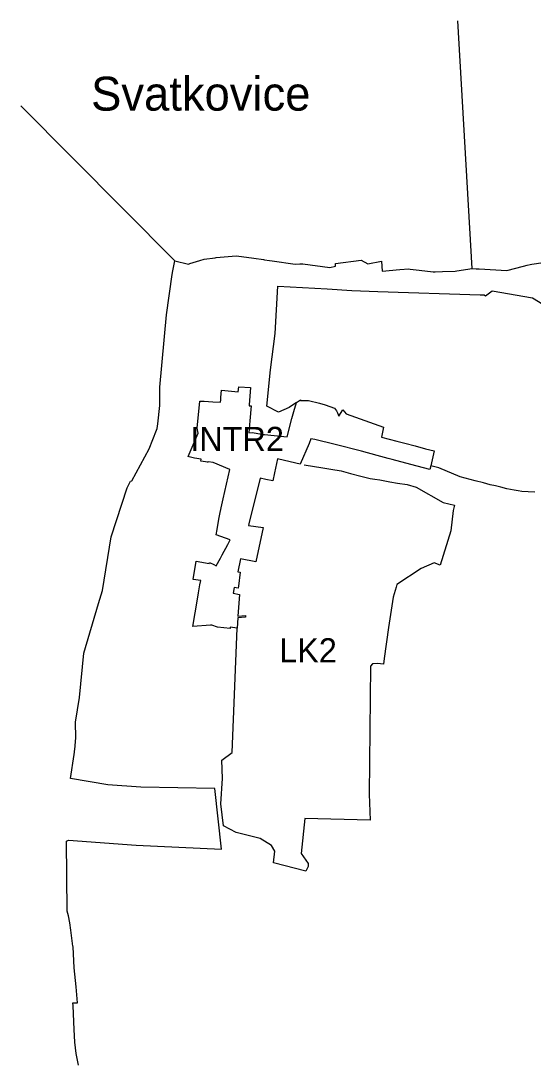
# Model space of a CAD drawing. Extents: x -761751 to -755187, y -1130961 to -1125705.
# Drawn here: x -758140 to -757082, y -1127845 to -1125705 of the extents above; entities that cross this region are included whole.
import ezdxf

# ---------------------------------------------------------------- set-up
doc = ezdxf.new("R2010")
doc.units = 0
for name, color, linetype in [('Vrstva 1', 7, 'Continuous'), ('Vrstva 13', 7, 'Continuous'), ('Vrstva 2', 7, 'Continuous'), ('Vrstva 3', 7, 'Continuous')]:
    doc.layers.add(name, color=color, linetype=linetype)

msp = doc.modelspace()

# ---------------------------------------------------------------- linework, layer by layer
at = {"layer": 'Vrstva 1'}
for p, q in [((-757208.02, -1126215.66), (-757237.56, -1125704.51)), ((-757761.4, -1126196.07), (-757738.61, -1126193.29)), ((-757738.61, -1126193.29), (-757736.19, -1126192.99)), ((-757736.19, -1126192.99), (-757694.99, -1126189.25)), ((-757694.99, -1126189.25), (-757683.91, -1126190.83)), ((-757683.91, -1126190.83), (-757658.81, -1126194.41)), ((-757658.81, -1126194.41), (-757638.53, -1126197.3)), ((-757825.98, -1126220.3), (-757821.94, -1126199.75)), ((-757821.94, -1126199.75), (-757793.4, -1126206.5)), ((-757793.4, -1126206.5), (-757790.46, -1126205.54)), ((-757790.46, -1126205.54), (-757770.03, -1126198.89)), ((-757770.03, -1126198.89), (-757761.4, -1126196.07)), ((-757638.53, -1126197.3), (-757636.67, -1126197.56)), ((-757636.67, -1126197.56), (-757626.07, -1126199.08)), ((-757626.07, -1126199.08), (-757621, -1126199.8)), ((-757621, -1126199.8), (-757573.19, -1126206.62)), ((-757573.19, -1126206.62), (-757563.97, -1126206.21)), ((-757563.97, -1126206.21), (-757557.49, -1126205.92)), ((-757557.49, -1126205.92), (-757501.9, -1126213.21)), ((-757501.9, -1126213.21), (-757489.88, -1126210.53)), ((-757489.96, -1126205.42), (-757437.34, -1126198.47)), ((-757489.88, -1126210.53), (-757489.96, -1126205.42)), ((-757437.34, -1126198.47), (-757423.25, -1126205.8)), ((-757423.25, -1126205.8), (-757395.12, -1126200.16)), ((-757395.12, -1126200.16), (-757394.08, -1126220.78)), ((-757239.65, -1126220.71), (-757208.02, -1126215.66)), ((-757208.02, -1126215.66), (-757199.86, -1126216.12)), ((-757136.53, -1126219.7), (-757102.22, -1126210.83)), ((-757102.22, -1126210.83), (-757094.46, -1126208.82)), ((-757094.46, -1126208.82), (-757088.47, -1126207.27)), ((-757088.47, -1126207.27), (-757084.65, -1126206.7)), ((-757084.65, -1126206.7), (-757038.05, -1126199.75)), ((-757838.75, -1126311.26), (-757827.03, -1126227.81)), ((-757827.03, -1126227.81), (-757825.98, -1126220.3)), ((-757394.08, -1126220.78), (-757357.14, -1126217.47)), ((-757357.14, -1126217.47), (-757338.76, -1126216.6)), ((-757338.76, -1126216.6), (-757335.77, -1126216.94)), ((-757335.77, -1126216.94), (-757317.68, -1126219.01)), ((-757317.68, -1126219.01), (-757288.67, -1126222.73)), ((-757288.67, -1126222.73), (-757284.71, -1126222.59)), ((-757284.71, -1126222.59), (-757269.1, -1126222.07)), ((-757269.1, -1126222.07), (-757243.17, -1126221.27)), ((-757243.17, -1126221.27), (-757239.65, -1126220.71)), ((-757199.86, -1126216.12), (-757196.23, -1126216.33)), ((-757196.23, -1126216.33), (-757193.87, -1126216.46)), ((-757193.87, -1126216.46), (-757136.53, -1126219.7)), ((-757852.7, -1126460.52), (-757838.75, -1126311.26)), ((-757852.52, -1126498.12), (-757852.7, -1126460.52)), ((-757857.01, -1126535.84), (-757852.52, -1126498.12)), ((-757858.2, -1126545.89), (-757857.01, -1126535.84)), ((-757874.52, -1126587.46), (-757859.3, -1126548.91)), ((-757859.3, -1126548.91), (-757858.2, -1126545.89)), ((-757910.13, -1126653.71), (-757874.52, -1126587.46)), ((-757919.77, -1126668.35), (-757913.33, -1126654.58)), ((-757913.33, -1126654.58), (-757910.13, -1126653.71)), ((-757953.22, -1126768.91), (-757919.77, -1126668.35)), ((-757971.1, -1126879.53), (-757953.22, -1126768.91)), ((-757979.21, -1126906.66), (-757971.1, -1126879.53)), ((-758009.73, -1127008.8), (-757979.21, -1126906.66)), ((-758018.14, -1127100.24), (-758009.73, -1127008.8)), ((-758026.73, -1127151.53), (-758018.14, -1127100.24)), ((-758026.19, -1127183.54), (-758026.73, -1127151.53)), ((-758028.28, -1127207.85), (-758026.19, -1127183.54)), ((-758037.17, -1127267.8), (-758029.39, -1127218.42)), ((-758029.39, -1127218.42), (-758028.78, -1127213.13)), ((-758028.78, -1127213.13), (-758028.59, -1127211.42)), ((-758028.59, -1127211.42), (-758028.28, -1127207.85)), ((-757959.77, -1127280.67), (-758037.17, -1127267.8)), ((-757891.62, -1127285.24), (-757959.77, -1127280.67)), ((-757739.13, -1127288.46), (-757891.62, -1127285.24)), ((-757725.26, -1127413.2), (-757739.13, -1127288.46)), ((-758044.98, -1127397.06), (-758041.39, -1127394.71)), ((-758043.73, -1127540.96), (-758044.98, -1127397.06)), ((-758041.39, -1127394.71), (-757901.27, -1127405.16)), ((-757901.27, -1127405.16), (-757725.26, -1127413.2)), ((-758040.99, -1127550.98), (-758043.73, -1127540.96)), ((-758038.05, -1127565.33), (-758040.99, -1127550.98)), ((-758036.04, -1127580.8), (-758038.05, -1127565.33)), ((-758031.82, -1127613.49), (-758036.04, -1127580.8)), ((-758031.78, -1127615.06), (-758031.82, -1127613.49)), ((-758029.63, -1127658.17), (-758031.78, -1127615.06)), ((-758024.94, -1127697.46), (-758029.63, -1127658.17)), ((-758022.65, -1127730.06), (-758024.94, -1127697.46)), ((-758032.13, -1127730.72), (-758026.99, -1127730.36)), ((-758031.54, -1127736.47), (-758032.13, -1127730.72)), ((-758026.99, -1127730.36), (-758022.65, -1127730.06)), ((-758029.67, -1127785.5), (-758031.54, -1127736.47)), ((-758027.86, -1127811.42), (-758029.67, -1127785.5)), ((-758025.49, -1127834.9), (-758027.86, -1127811.42)), ((-758020.54, -1127858.91), (-758025.49, -1127834.9))]:
    msp.add_line(p, q, dxfattribs=at)
msp.add_lwpolyline([(-757821.94, -1126199.75), (-758139.65, -1125879.99), (-758139.65, -1125879.99)], dxfattribs=at)
at = {"layer": 'Vrstva 2'}
for points in [[(-757769.76, -1126868.03), (-757768.27, -1126858.9), (-757784.13, -1126856.88), (-757777.33, -1126819.29), (-757750.54, -1126824.03), (-757749.9, -1126821.92), (-757741.53, -1126826.15), (-757736.04, -1126829.24), (-757727.63, -1126813.32), (-757724.28, -1126806.08), (-757712.63, -1126784.92), (-757707.58, -1126775.37), (-757736.27, -1126764.99), (-757734.24, -1126754.01), (-757732.6, -1126745.31), (-757730.36, -1126729.57), (-757727.79, -1126719.2), (-757724.48, -1126702.92), (-757721.9, -1126690.94), (-757714.74, -1126660.16), (-757711.44, -1126645.34), (-757707.97, -1126629.9), (-757742.81, -1126615.55), (-757752.59, -1126614.39), (-757752.74, -1126615.41), (-757755.11, -1126615.1), (-757758.37, -1126614.51), (-757767.74, -1126612.72), (-757767.11, -1126609.02), (-757780.98, -1126606.66), (-757783.72, -1126606.08), (-757792.22, -1126603.86), (-757794.04, -1126603.39), (-757773.56, -1126555.23), (-757775.48, -1126544.74), (-757770.07, -1126488.95), (-757761.34, -1126489.48), (-757743.23, -1126490.51), (-757727.65, -1126491.47), (-757727.01, -1126486.62), (-757726.67, -1126482.03), (-757725.18, -1126466.5), (-757690.66, -1126470.24), (-757689.63, -1126459.39), (-757665.52, -1126461.27), (-757668.22, -1126496.71), (-757668.3, -1126498.69)], [(-757639.26, -1126557.77), (-757636.38, -1126558.18), (-757589.54, -1126562.57), (-757580.04, -1126525.3), (-757575.82, -1126510.61), (-757570.62, -1126492.02), (-757562.4, -1126486.79), (-757562.53, -1126488.03), (-757545.91, -1126488.14), (-757523.45, -1126493.36), (-757511.36, -1126497.12), (-757492.4, -1126504.01), (-757488.02, -1126509.38), (-757486.31, -1126513.4), (-757483.28, -1126520.09), (-757474.74, -1126507.05), (-757468.03, -1126515.06), (-757391.02, -1126542.91), (-757395.15, -1126563.3), (-757363.56, -1126571.77), (-757346.79, -1126576.2), (-757325.65, -1126581.62), (-757304.21, -1126587.27), (-757286.34, -1126591.69)], [(-757668.3, -1126498.69), (-757664.22, -1126499.14), (-757666.61, -1126529.72)], [(-757666.61, -1126529.72), (-757668.87, -1126554.44), (-757661.4, -1126554.16), (-757643.16, -1126557.05), (-757639.26, -1126557.77)], [(-757286.34, -1126591.69), (-757293.32, -1126622.31), (-757295.23, -1126630.53), (-757334.92, -1126619.97), (-757372.95, -1126609.65), (-757381.37, -1126607.51), (-757404.27, -1126601.52), (-757436.52, -1126592.69), (-757490.74, -1126578.72), (-757533.01, -1126568.2), (-757541.2, -1126567.22), (-757544.58, -1126576.78), (-757562.98, -1126618.89), (-757571.8, -1126617.12), (-757609.61, -1126608.5)], [(-757609.61, -1126608.5), (-757615.9, -1126637.05), (-757619.3, -1126653.41)], [(-757645.69, -1126647.8), (-757668.79, -1126742.24), (-757669.76, -1126745.79), (-757639.55, -1126749.83), (-757654.27, -1126820.72), (-757686.09, -1126814.71), (-757691.93, -1126841.42), (-757687.18, -1126842.19), (-757690.21, -1126870.74), (-757690.92, -1126875.07), (-757699, -1126873.37)], [(-757619.3, -1126653.41), (-757633.97, -1126650.65), (-757645.69, -1126647.8)], [(-757774.93, -1126897.53), (-757772.71, -1126884.96), (-757769.76, -1126868.03)], [(-757699, -1126873.37), (-757701.57, -1126885.49), (-757688.26, -1126887.75), (-757691.37, -1126932.68)], [(-757745.14, -1126951.43), (-757748.28, -1126951.1), (-757784.51, -1126953.94), (-757774.93, -1126897.53)], [(-757676.16, -1126935.01), (-757691.57, -1126936.5), (-757693, -1126957.49), (-757707.5, -1126955.73), (-757707.65, -1126957.98), (-757733.78, -1126955.31), (-757745.14, -1126951.43)], [(-757691.37, -1126932.68), (-757675.94, -1126931.43), (-757676.16, -1126935.01)]]:
    msp.add_lwpolyline(points, dxfattribs=at)
at = {"layer": 'Vrstva 3'}
for points in [[(-757570.62, -1126492.02), (-757585.89, -1126502.21), (-757607.98, -1126511.9), (-757631.82, -1126499.83), (-757631.82, -1126499.83), (-757624.4, -1126424.32), (-757614.86, -1126349.33), (-757608.83, -1126252.02), (-757608.83, -1126252.02), (-757507.53, -1126257.83), (-757456.22, -1126260.89), (-757402.86, -1126263.17)], [(-757402.86, -1126263.17), (-757402.86, -1126263.17), (-757191.87, -1126270.02), (-757183.32, -1126269.83), (-757180.72, -1126272.17), (-757180.72, -1126272.17), (-757166.5, -1126261.73), (-757083.67, -1126276.31), (-756961.23, -1126350.96)], [(-757554.54, -1126620.76), (-757533.34, -1126624.02), (-757520.72, -1126626.13), (-757499.47, -1126629.52), (-757478.21, -1126633.04), (-757459.48, -1126638.37), (-757438.05, -1126643.91), (-757418.39, -1126648.76), (-757408.61, -1126650.25), (-757398.43, -1126651.87), (-757377.97, -1126655.54), (-757362.37, -1126658.06), (-757342.16, -1126661.45), (-757323.45, -1126666.56), (-757267.93, -1126698.16), (-757267.93, -1126698.16), (-757244.58, -1126703.81), (-757247.6, -1126714.76), (-757252.4, -1126756.63), (-757273.93, -1126827.39), (-757286.46, -1126822.84), (-757313.2, -1126834.68), (-757363.44, -1126867.22), (-757364.88, -1126873.09), (-757370.94, -1126893.91), (-757380.93, -1126956.38), (-757389.4, -1127019.82), (-757391.07, -1127031.59), (-757403.57, -1127030.19), (-757413.48, -1127030.93), (-757417.88, -1127035.57), (-757420.43, -1127299.69), (-757418.24, -1127353.77), (-757553.51, -1127350.02), (-757561, -1127422.34), (-757546.3, -1127442.64), (-757546.21, -1127449.09), (-757546.21, -1127449.09), (-757551.22, -1127458.98), (-757617.73, -1127441.28), (-757615.31, -1127417.84), (-757622.25, -1127405.91), (-757645.41, -1127391.2), (-757695.25, -1127379.03), (-757695.25, -1127379.03), (-757721.35, -1127365.32), (-757726.52, -1127320.13), (-757723.54, -1127267.52), (-757724.47, -1127229.89), (-757703.44, -1127213.94), (-757693, -1126957.49)], [(-757079.08, -1126676.68), (-757092.45, -1126676.12), (-757105.69, -1126675.52), (-757113.43, -1126674.39), (-757121.55, -1126672.76), (-757121.55, -1126672.76), (-757136.78, -1126669.98), (-757148.85, -1126666.96), (-757160.02, -1126663.83), (-757170.93, -1126661.51), (-757185.01, -1126657.65), (-757201.82, -1126653.29), (-757232.54, -1126645.6), (-757276.56, -1126627), (-757293.32, -1126622.31)]]:
    msp.add_lwpolyline(points, dxfattribs=at)

# ---------------------------------------------------------------- texts
at = {"layer": 'Vrstva 1'}
msp.add_text('Svatkovice', height=70, dxfattribs=at).set_placement((-757994.44, -1125889.92))
at = {"layer": 'Vrstva 13'}
for s, p in [('INTR2', (-757789.77, -1126592.21)), ('LK2', (-757606.26, -1127028.29))]:
    msp.add_text(s, height=50, dxfattribs=at).set_placement(p)

doc.saveas('drawing.dxf')
